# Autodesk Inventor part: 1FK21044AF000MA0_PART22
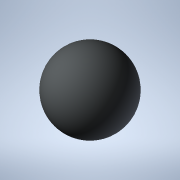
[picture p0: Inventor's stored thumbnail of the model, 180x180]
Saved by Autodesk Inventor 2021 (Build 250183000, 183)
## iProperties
Created: 2025-04
Part Number: 1FK21044AF000MA0_PART22
Material: Generic
Catalog Web Link: www.3dfindit.com
Description: -Servo synchronous motor
Document SubType Name: Modeling
Designer: psAdmin
Mass: 0.137258 g
Surface Area: 1.2868 cm^2
Volume: 0.137258 cm^3
Density: 1 g/cm^3
Appearance: PSOLRGB-212-217-219
Category: PARTsolutions
Title: 1FK21044AF000MA0_PART22
Author: Cadenas PARTsolutions
Comments: Servo synchronous motor
Sending System: PARTsolutions
Preprocessor: ST-DEVELOPER v19.3
PSOL_IDENT_0: {$CADENAS_DATA/23d-libs/siemens_ag/_cat_/39/c4/1fk21044af000ma0.prj},216 {VTYP=3D},{NB=1FK21044AF000
PSOL_IDENT_1: MA0_PART22},{LINA=1FK21044AF000MA0_PART22},{NN=1FK21044AF000MA0_PART22},{NOPRJ=TRUE},{DATE=19.08.202
PSOL_IDENT_2: 5 14:00:33},{GEOMDATE=30.07.2025 02:02:22},{VERSION=},{LINEID=10},{WBVAR=},{WBNUMERIC=}  {NB=1FK2104
PSOL_IDENT_3: 4AF000MA0_PART22},{LINA=1FK21044AF000MA0_PART22},{KT=DUMMY},{PREVIEW=../../../_pool_/cb/72/p_d211_xx
PSOL_IDENT_4: _00434j.png},{DESCSHORT=SIMOTICS S-1FK2 HD, SINAMICS S210 3AC 400V-480V, 1.27 Nm, 3000 rpm},{DESCLON
PSOL_IDENT_5: G=SIMOTICS S-1FK2 HD servo motor M0=1.27 Nm; PN = 0.4 kW at nN=3000 rpm (380-480 V); PN = 0.2 kW at
PSOL_IDENT_6: nN=1500 rpm (200-240 V); degree of protection IP64; cylindrical shaft D19x40mm; absolute encoder 22-
PSOL_IDENT_7: bit + 12-bit multiturn (encoder AM22DQC); with OCC interface; plug size M17, rotatable; SIMOTICS S-1
PSOL_IDENT_8: FK2 servomotorfor a wide range of uses in industrial environments. SIMOTICS S‑1FK2 servomotors are c
PSOL_IDENT_9: ompact synchronous motors with a high dynamic performance that set themselves apart as a result of t
PSOL_IDENT_10: heir high power density, degree of protection and overload capability. The motors are available in t
PSOL_IDENT_11: wo variants: as High Dynamic variant (highest dynamic performance as a result of the low intrinsic m
PSOL_IDENT_12: oment of inertia for applications demanding a high dynamic performance with low moved masses) - and
PSOL_IDENT_13: as Compact variant (precise and stable closed-loop control for medium up to large moved masses as a
PSOL_IDENT_14: result of a medium intrinsic moment of inertia). SIMOTICSS‑1FK2 servomotors fully exploit their stre
PSOL_IDENT_15: ngths in a system with the SINAMICSS210 frequency converter and simple connection using the one cabl
PSOL_IDENT_16: e connection (OCC). Advantages include the short control and positioning times, fast and precise cor
PSOL_IDENT_17: rection of disturbing quantities as well as stable control with a high dynamic performance. The serv
PSOL_IDENT_18: o motors can be configured to address a wide range of requirements. For example with and without hol
PSOL_IDENT_19: ding brake, IP64 or IP65 degree of protection, singleturn or multiturn absolute encoders - to name j
PSOL_IDENT_20: ust a few. Further, the servomotors are available in different shaft heights extending from 20 to 10
PSOL_IDENT_21: 0. A shaft sealing ring is available to achieve an IP65 degree of protection and for subsequent moun
PSOL_IDENT_22: ting at the motor or as spare part. SIMOTICS - the optimum motor for each and every motion control a
PSOL_IDENT_23: pplication.},{INTNO=804766906428},{SUPPLIERALTNO=1FK2104-4AF00-0MA0},{MANUID=1FK21044AF000MA0},{MANU
PSOL_IDENT_24: NAME=Siemens},{MANUTYPEDESC=Synchronous motor 1FK2-HD 1.27 NM},{AAU732=SIMOTICS},{AAO057=S-1FK2},{AA
PSOL_IDENT_25: U734=SIMOTICS S-1FK2 HD servo motor M0=1.27 Nm; PN = 0.4 kW at nN=3000 rpm (380-480 V); PN = 0.2 kW
PSOL_IDENT_26: at nN=1500 rpm (200-240 V); degree of protection IP64; cylindrical shaft D19x40mm; absolute encoder
PSOL_IDENT_27: 22-bit + 12-bit multiturn (encoder AM22DQC); with OCC interface; plug size M17, rotatable;},{AAW338=
PSOL_IDENT_28: Synchronous motor 1FK2-HD 1.27 NM},{AAO742=SIMOTICS},{AAO663=4042948693322},{NOCUPEROU=1},{PRICEQUAN
PSOL_IDENT_29: TITY=1},{QUANTITYMIN=1},{QUANTITYINT=1},{CTN=85015100},{COO=DE},{AAO676=1FK2104-4AF00-0MA0},{AAO677=
PSOL_IDENT_30: Siemens AG},{ORDERUNIT=C62},{CONTENTUNIT=C62}
NB: 1FK21044AF000MA0_PART22
NT: Servo synchronous motor
NBSYN: $MANUID._PART22
LINA: 1FK21044AF000MA0_PART22
CATALOG: SIEMENS
PREVIEW: ../../../_pool_/cb/72/p_d211_xx_00434j.png
DESCSHORT: SIMOTICS S-1FK2 HD, SINAMICS S210 3AC 400V-480V, 1.27 Nm, 3000 rpm
DESCLONG: SIMOTICS S-1FK2 HD servo motor M0=1.27 Nm; PN = 0.4 kW at nN=3000 rpm (380-480 V); PN = 0.2 kW at nN=1500 rpm (200-240 V); degree of protection IP64; cylindrica
INTNO: 804766906428
SUPPLIERALTNO: 1FK2104-4AF00-0MA0
MANUID: 1FK21044AF000MA0
MANUNAME: Siemens
MANUTYPEDESC: Synchronous motor 1FK2-HD 1.27 NM
AAU732: SIMOTICS
AAO057: S-1FK2
AAU734: SIMOTICS S-1FK2 HD servo motor M0=1.27 Nm; PN = 0.4 kW at nN=3000 rpm (380-480 V); PN = 0.2 kW at nN=1500 rpm (200-240 V); degree of protection IP64; cylindrica
AAW338: Synchronous motor 1FK2-HD 1.27 NM
AAO742: SIMOTICS
AAO663: 4042948693322.0
NOCUPEROU: 1
PRICEQUANTITY: 1
QUANTITYMIN: 1
QUANTITYINT: 1
CTN: 85015100
COO: DE
ARTICLENO: 1FK21044AF000MA0_PART22
BOMINFO: 1FK21044AF000MA0_PART22
CREATOR: CADENAS GmbH
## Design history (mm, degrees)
feature "2025_04_17_15_01_28_0038"
body "Solid1"
